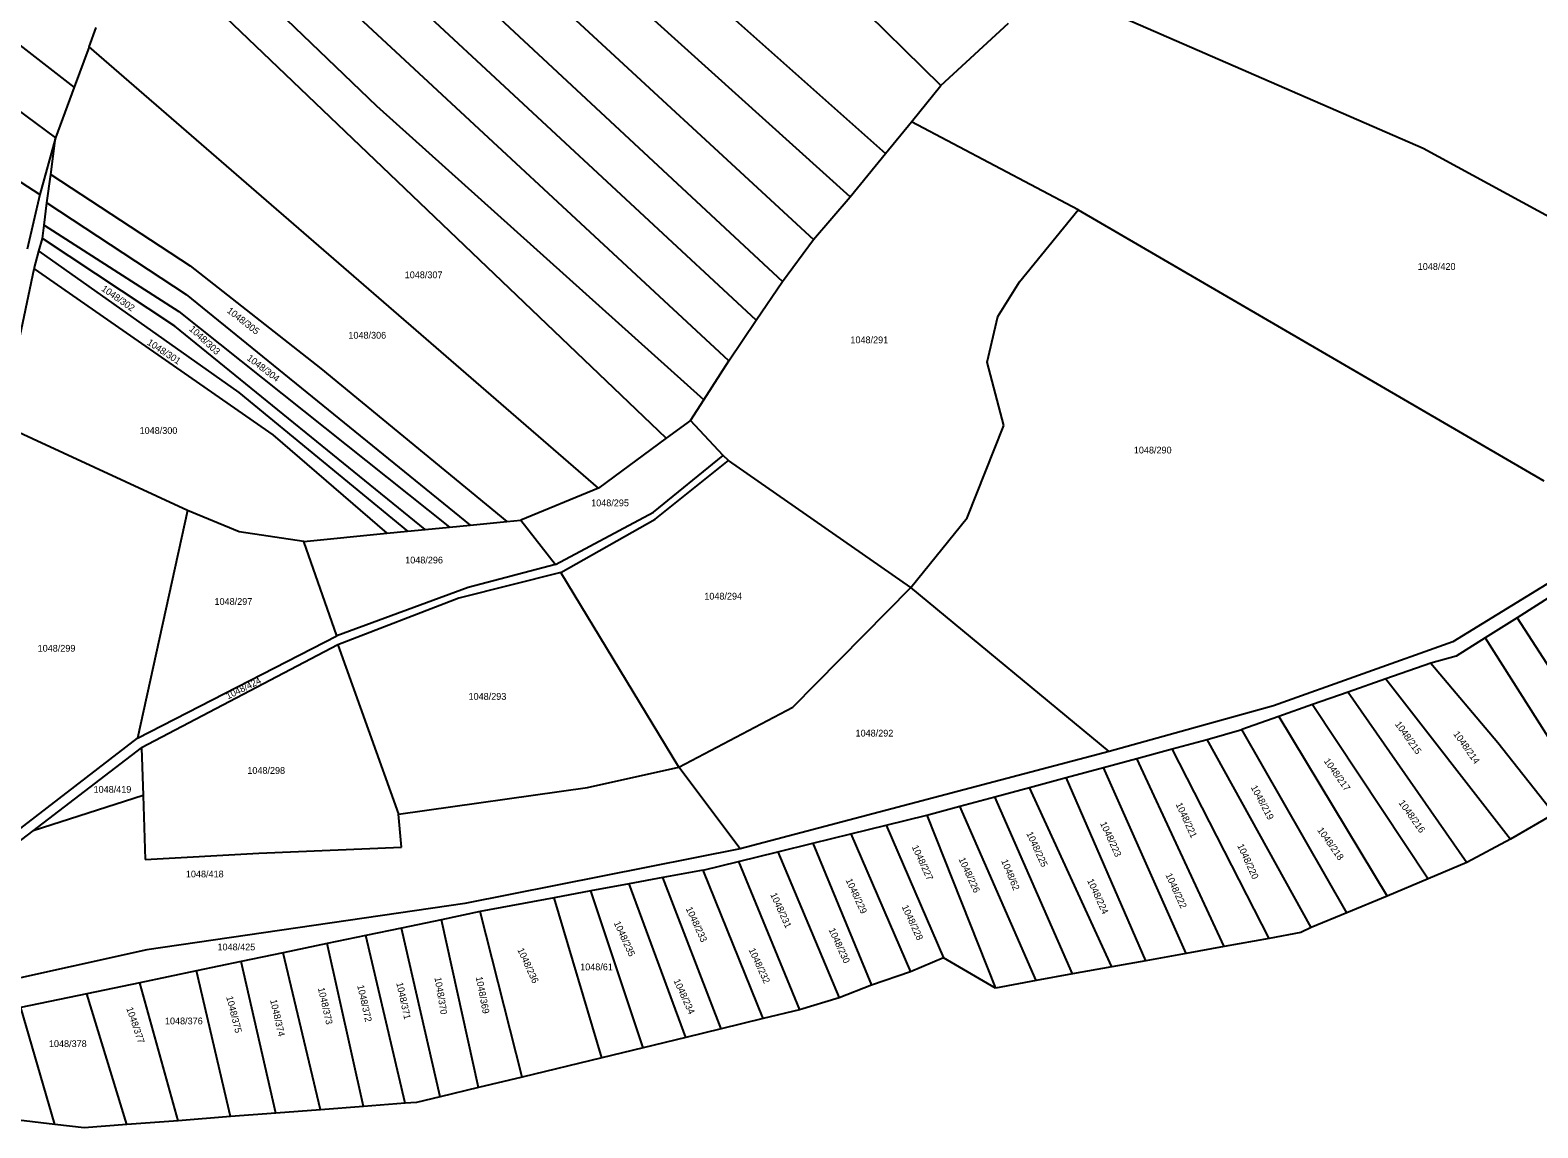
# Model space of a CAD drawing. Extents: x -580630 to -576196, y -1189024 to -1183567.
# Drawn here: x -577659.8 to -577281.4, y -1186719.7 to -1186444.2 of the extents above; entities that cross this region are included whole.
import ezdxf

# ---------------------------------------------------------------- set-up
doc = ezdxf.new("R2010")
doc.units = 0
for name, color, linetype in [('Vrstva 1', 7, 'Continuous'), ('Vrstva 18', 7, 'Continuous'), ('Vrstva 6', 7, 'Continuous')]:
    doc.layers.add(name, color=color, linetype=linetype)

msp = doc.modelspace()

# ---------------------------------------------------------------- linework, layer by layer
at = {"layer": 'Vrstva 1'}
for p, q in [((-577277.78, -1186586.1), (-577286.64, -1186591.67)), ((-577286.64, -1186591.67), (-577294.65, -1186596.71)), ((-577294.65, -1186596.71), (-577301.89, -1186601.27)), ((-577301.89, -1186601.27), (-577308.25, -1186603.03)), ((-577308.25, -1186603.03), (-577291.48, -1186622.95)), ((-577291.48, -1186622.95), (-577277.31, -1186640.88)), ((-577426.5, -1186638.96), (-577417.72, -1186636.58)), ((-577398.18, -1186681.03), (-577417.72, -1186636.58)), ((-577407.33, -1186682.72), (-577426.5, -1186638.96)), ((-577277.31, -1186640.88), (-577288.28, -1186647.21)), ((-577288.28, -1186647.21), (-577299.24, -1186653.09)), ((-577299.24, -1186653.09), (-577308.96, -1186657.2)), ((-577308.96, -1186657.2), (-577319.21, -1186661.48)), ((-577519.08, -1186660.17), (-577528.29, -1186661.93)), ((-577505.98, -1186699.57), (-577519.08, -1186660.17)), ((-577516.38, -1186702.1), (-577528.29, -1186661.93)), ((-577319.21, -1186661.48), (-577329.36, -1186665.67)), ((-577329.36, -1186665.67), (-577338.27, -1186669.41)), ((-577348.86, -1186672.11), (-577360.12, -1186674.15)), ((-577340.93, -1186670.67), (-577348.86, -1186672.11)), ((-577338.27, -1186669.41), (-577340.93, -1186670.67)), ((-577369.67, -1186675.89), (-577379.81, -1186677.73)), ((-577360.12, -1186674.15), (-577369.67, -1186675.89)), ((-577430.58, -1186677), (-577438.85, -1186680.47)), ((-577417.57, -1186684.58), (-577430.58, -1186677)), ((-577388.31, -1186679.27), (-577398.18, -1186681.03)), ((-577379.81, -1186677.73), (-577388.31, -1186679.27)), ((-577448.65, -1186683.86), (-577456.76, -1186687.07)), ((-577438.85, -1186680.47), (-577448.65, -1186683.86)), ((-577407.33, -1186682.72), (-577417.57, -1186684.58)), ((-577398.18, -1186681.03), (-577407.33, -1186682.72)), ((-577456.76, -1186687.07), (-577466.74, -1186690.01)), ((-577466.74, -1186690.01), (-577475.83, -1186692.24)), ((-577486.37, -1186694.8), (-577495.23, -1186696.96)), ((-577475.83, -1186692.24), (-577486.37, -1186694.8)), ((-577495.23, -1186696.96), (-577505.98, -1186699.57)), ((-577516.38, -1186702.1), (-577536.34, -1186706.96)), ((-577505.98, -1186699.57), (-577516.38, -1186702.1)), ((-577547.3, -1186709.57), (-577556.96, -1186711.88)), ((-577536.34, -1186706.96), (-577547.3, -1186709.57)), ((-577576.15, -1186714.3), (-577586.92, -1186715.12)), ((-577565.72, -1186713.5), (-577576.15, -1186714.3)), ((-577562.83, -1186713.28), (-577565.72, -1186713.5)), ((-577556.96, -1186711.88), (-577562.83, -1186713.28)), ((-577653.65, -1186718.79), (-577670.26, -1186716.82)), ((-577622.7, -1186717.86), (-577635.57, -1186718.84)), ((-577609.57, -1186716.85), (-577622.7, -1186717.86)), ((-577598.15, -1186715.98), (-577609.57, -1186716.85)), ((-577586.92, -1186715.12), (-577598.15, -1186715.98)), ((-577646.26, -1186719.66), (-577653.65, -1186718.79)), ((-577635.57, -1186718.84), (-577646.26, -1186719.66))]:
    msp.add_line(p, q, dxfattribs=at)
at = {"layer": 'Vrstva 6'}
for p, q in [((-577589.77, -1186379.94), (-577463.21, -1186496.69)), ((-577454.01, -1186485.99), (-577572.08, -1186379.63)), ((-577602.85, -1186384.5), (-577471.03, -1186507.3)), ((-577477.58, -1186516.94), (-577617.31, -1186387.27)), ((-577572.78, -1186463.24), (-577649.25, -1186389.86)), ((-577484.5, -1186527.2), (-577630.78, -1186391.29)), ((-577522.55, -1186406.3), (-577445.14, -1186475.12)), ((-577431.26, -1186458.1), (-577483.66, -1186406.54)), ((-577500.2, -1186546.6), (-577634.12, -1186418.61)), ((-577648.78, -1186458.48), (-577691.75, -1186425.18)), ((-577705.7, -1186432.42), (-577653.48, -1186471.22)), ((-577403.23, -1186433.27), (-577310.18, -1186473.84)), ((-577645.05, -1186448.38), (-577643.26, -1186443.5)), ((-577431.26, -1186458.1), (-577414.28, -1186442.43)), ((-577645.05, -1186448.38), (-577648.78, -1186458.48)), ((-577517.19, -1186559.12), (-577645.05, -1186448.38)), ((-577648.78, -1186458.48), (-577653.48, -1186471.22)), ((-577438.65, -1186467.16), (-577431.26, -1186458.1)), ((-577490.73, -1186536.97), (-577572.78, -1186463.24)), ((-577445.14, -1186475.12), (-577438.65, -1186467.16)), ((-577396.82, -1186489.29), (-577438.65, -1186467.16)), ((-577681.11, -1186470.11), (-577657.44, -1186485.43)), ((-577653.48, -1186471.22), (-577657.44, -1186485.43)), ((-577654.68, -1186480.42), (-577653.48, -1186471.22)), ((-577454.01, -1186485.99), (-577445.14, -1186475.12)), ((-577310.18, -1186473.84), (-577222.05, -1186521.64)), ((-577655.61, -1186487.52), (-577654.68, -1186480.42)), ((-577654.68, -1186480.42), (-577619.66, -1186503.3)), ((-577657.44, -1186485.43), (-577660.59, -1186499.11)), ((-577463.21, -1186496.69), (-577454.01, -1186485.99)), ((-577656.33, -1186493.09), (-577655.61, -1186487.52)), ((-577655.61, -1186487.52), (-577620.71, -1186510.54)), ((-577411.52, -1186507.32), (-577396.82, -1186489.29)), ((-577396.82, -1186489.29), (-577279.9, -1186557.31)), ((-577656.77, -1186496.44), (-577656.33, -1186493.09)), ((-577656.33, -1186493.09), (-577622.55, -1186514.75)), ((-577657.64, -1186499.65), (-577656.77, -1186496.44)), ((-577623.48, -1186518.44), (-577656.77, -1186496.44)), ((-577471.03, -1186507.3), (-577463.21, -1186496.69)), ((-577658.85, -1186504.08), (-577657.64, -1186499.65)), ((-577657.64, -1186499.65), (-577607.42, -1186535.1)), ((-577667.06, -1186543.16), (-577658.85, -1186504.08)), ((-577658.85, -1186504.08), (-577598.93, -1186545.77)), ((-577619.66, -1186503.3), (-577586.88, -1186529.11)), ((-577477.58, -1186516.94), (-577471.03, -1186507.3)), ((-577416.91, -1186516.08), (-577411.52, -1186507.32)), ((-577620.71, -1186510.54), (-577549.43, -1186568.41)), ((-577622.55, -1186514.75), (-577554.59, -1186568.91)), ((-577484.5, -1186527.2), (-577477.58, -1186516.94)), ((-577419.6, -1186527.54), (-577416.91, -1186516.08)), ((-577560.73, -1186569.51), (-577623.48, -1186518.44)), ((-577490.73, -1186536.97), (-577484.5, -1186527.2)), ((-577415.42, -1186543.38), (-577419.6, -1186527.54)), ((-577586.88, -1186529.11), (-577540.16, -1186567.5)), ((-577607.42, -1186535.1), (-577565.14, -1186569.95)), ((-577494.11, -1186542.12), (-577490.73, -1186536.97)), ((-577620.3, -1186564.71), (-577667.06, -1186543.16)), ((-577494.11, -1186542.12), (-577500.2, -1186546.6)), ((-577485.86, -1186550.96), (-577494.11, -1186542.12)), ((-577424.63, -1186566.57), (-577415.42, -1186543.38)), ((-577598.93, -1186545.77), (-577570.3, -1186570.45)), ((-577500.2, -1186546.6), (-577517.19, -1186559.12)), ((-577503.37, -1186565.18), (-577485.86, -1186550.96)), ((-577484.57, -1186552.19), (-577485.86, -1186550.96)), ((-577502.98, -1186566.94), (-577484.57, -1186552.19)), ((-577438.76, -1186584.06), (-577484.57, -1186552.19)), ((-577517.19, -1186559.12), (-577536.66, -1186567.16)), ((-577620.3, -1186564.71), (-577632.87, -1186621.83)), ((-577607.34, -1186570.07), (-577620.3, -1186564.71)), ((-577527.98, -1186578.29), (-577503.37, -1186565.18)), ((-577438.76, -1186584.06), (-577424.63, -1186566.57)), ((-577591.16, -1186572.49), (-577607.34, -1186570.07)), ((-577591.16, -1186572.49), (-577570.3, -1186570.45)), ((-577570.3, -1186570.45), (-577565.14, -1186569.95)), ((-577565.14, -1186569.95), (-577560.73, -1186569.51)), ((-577560.73, -1186569.51), (-577554.59, -1186568.91)), ((-577554.59, -1186568.91), (-577549.43, -1186568.41)), ((-577549.43, -1186568.41), (-577540.16, -1186567.5)), ((-577540.16, -1186567.5), (-577536.66, -1186567.16)), ((-577536.66, -1186567.16), (-577527.98, -1186578.29)), ((-577526.63, -1186580.31), (-577502.98, -1186566.94)), ((-577582.87, -1186596.15), (-577591.16, -1186572.49)), ((-577526.63, -1186580.31), (-577552.23, -1186586.72)), ((-577527.98, -1186578.29), (-577549.87, -1186584.02)), ((-577497, -1186629.18), (-577526.63, -1186580.31)), ((-577549.87, -1186584.02), (-577582.87, -1186596.15)), ((-577468.4, -1186614.05), (-577438.76, -1186584.06)), ((-577388.98, -1186625.22), (-577438.76, -1186584.06)), ((-577276.97, -1186581.88), (-577302.76, -1186597.69)), ((-577552.23, -1186586.72), (-577582.6, -1186598.42)), ((-577286.64, -1186591.67), (-577269.26, -1186618.5)), ((-577632.87, -1186621.83), (-577582.87, -1186596.15)), ((-577294.65, -1186596.71), (-577277.24, -1186624.1)), ((-577582.6, -1186598.42), (-577631.87, -1186624.32)), ((-577582.6, -1186598.42), (-577567.34, -1186640.96)), ((-577302.76, -1186597.69), (-577347.78, -1186613.75)), ((-577308.25, -1186603.03), (-577319.58, -1186607)), ((-577319.58, -1186607), (-577329.02, -1186610.3)), ((-577319.58, -1186607), (-577288.28, -1186647.21)), ((-577329.02, -1186610.3), (-577337.96, -1186613.43)), ((-577329.02, -1186610.3), (-577299.24, -1186653.09)), ((-577497, -1186629.18), (-577468.4, -1186614.05)), ((-577347.78, -1186613.75), (-577388.98, -1186625.22)), ((-577337.96, -1186613.43), (-577346.43, -1186616.4)), ((-577337.96, -1186613.43), (-577308.96, -1186657.2)), ((-577364.38, -1186622.16), (-577355.74, -1186619.66)), ((-577346.43, -1186616.4), (-577355.74, -1186619.66)), ((-577329.36, -1186665.67), (-577355.74, -1186619.66)), ((-577346.43, -1186616.4), (-577319.21, -1186661.48)), ((-577684.08, -1186661.26), (-577632.87, -1186621.83)), ((-577373.16, -1186624.53), (-577364.38, -1186622.16)), ((-577338.27, -1186669.41), (-577364.38, -1186622.16)), ((-577659.08, -1186645.09), (-577631.87, -1186624.32)), ((-577631.87, -1186624.32), (-577631.48, -1186636.25)), ((-577388.98, -1186625.22), (-577481.66, -1186649.65)), ((-577390.45, -1186629.21), (-577382.04, -1186626.94)), ((-577382.04, -1186626.94), (-577373.16, -1186624.53)), ((-577360.12, -1186674.15), (-577382.04, -1186626.94)), ((-577348.86, -1186672.11), (-577373.16, -1186624.53)), ((-577519.96, -1186634.24), (-577497, -1186629.18)), ((-577481.66, -1186649.65), (-577497, -1186629.18)), ((-577399.77, -1186631.73), (-577390.45, -1186629.21)), ((-577369.67, -1186675.89), (-577390.45, -1186629.21)), ((-577567.34, -1186640.96), (-577519.96, -1186634.24)), ((-577417.72, -1186636.58), (-577409.02, -1186634.23)), ((-577409.02, -1186634.23), (-577399.77, -1186631.73)), ((-577388.31, -1186679.27), (-577409.02, -1186634.23)), ((-577379.81, -1186677.73), (-577399.77, -1186631.73)), ((-577631.48, -1186636.25), (-577659.08, -1186645.09)), ((-577631.48, -1186636.25), (-577630.96, -1186652.29)), ((-577566.6, -1186649.26), (-577567.34, -1186640.96)), ((-577444.96, -1186643.69), (-577434.76, -1186641.19)), ((-577434.76, -1186641.19), (-577426.5, -1186638.96)), ((-577434.76, -1186641.19), (-577417.57, -1186684.58)), ((-577686.2, -1186665.78), (-577659.08, -1186645.09)), ((-577463.41, -1186648.22), (-577453.81, -1186645.87)), ((-577453.81, -1186645.87), (-577444.96, -1186643.69)), ((-577453.81, -1186645.87), (-577438.85, -1186680.47)), ((-577444.96, -1186643.69), (-577430.58, -1186677)), ((-577602.4, -1186650.75), (-577566.6, -1186649.26)), ((-577481.66, -1186649.65), (-577550.71, -1186663.38)), ((-577472.2, -1186650.38), (-577463.41, -1186648.22)), ((-577463.41, -1186648.22), (-577448.65, -1186683.86)), ((-577630.96, -1186652.29), (-577602.4, -1186650.75)), ((-577490.89, -1186654.97), (-577482.01, -1186652.79)), ((-577482.01, -1186652.79), (-577472.2, -1186650.38)), ((-577482.01, -1186652.79), (-577466.74, -1186690.01)), ((-577472.2, -1186650.38), (-577456.76, -1186687.07)), ((-577501.03, -1186656.86), (-577509.51, -1186658.44)), ((-577490.89, -1186654.97), (-577501.03, -1186656.86)), ((-577486.37, -1186694.8), (-577501.03, -1186656.86)), ((-577475.83, -1186692.24), (-577490.89, -1186654.97)), ((-577509.51, -1186658.44), (-577519.08, -1186660.17)), ((-577495.23, -1186696.96), (-577509.51, -1186658.44)), ((-577550.71, -1186663.38), (-577630.52, -1186675)), ((-577528.29, -1186661.93), (-577546.92, -1186665.4)), ((-577556.63, -1186667.43), (-577566.66, -1186669.53)), ((-577546.92, -1186665.4), (-577556.63, -1186667.43)), ((-577547.3, -1186709.57), (-577556.63, -1186667.43)), ((-577536.34, -1186706.96), (-577546.92, -1186665.4)), ((-577575.57, -1186671.39), (-577585.3, -1186673.42)), ((-577566.66, -1186669.53), (-577575.57, -1186671.39)), ((-577565.72, -1186713.5), (-577575.57, -1186671.39)), ((-577556.96, -1186711.88), (-577566.66, -1186669.53)), ((-577630.52, -1186675), (-577681.26, -1186686.16)), ((-577596.32, -1186675.72), (-577606.9, -1186677.93)), ((-577585.3, -1186673.42), (-577596.32, -1186675.72)), ((-577586.92, -1186715.12), (-577596.32, -1186675.72)), ((-577576.15, -1186714.3), (-577585.3, -1186673.42)), ((-577606.9, -1186677.93), (-577618.05, -1186680.26)), ((-577598.15, -1186715.98), (-577606.9, -1186677.93)), ((-577632.34, -1186683.25), (-577645.62, -1186686.02)), ((-577618.05, -1186680.26), (-577632.34, -1186683.25)), ((-577622.7, -1186717.86), (-577632.34, -1186683.25)), ((-577609.57, -1186716.85), (-577618.05, -1186680.26)), ((-577645.62, -1186686.02), (-577662.17, -1186689.48)), ((-577635.57, -1186718.84), (-577645.62, -1186686.02)), ((-577653.65, -1186718.79), (-577662.17, -1186689.48))]:
    msp.add_line(p, q, dxfattribs=at)

# ---------------------------------------------------------------- texts
at = {"layer": 'Vrstva 18'}
for s, p in [('1048/307', (-577565.82, -1186506.44)), ('1048/420', (-577311.557, -1186504.35)), ('1048/306', (-577579.96, -1186521.6)), ('1048/291', (-577453.952, -1186522.76)), ('1048/300', (-577632.367, -1186545.51)), ('1048/290', (-577382.817, -1186550.42)), ('1048/295', (-577519.027, -1186563.67)), ('1048/296', (-577565.7, -1186578.02)), ('1048/294', (-577490.63, -1186587.09)), ('1048/297', (-577613.56, -1186588.42)), ('1048/299', (-577657.96, -1186600.16)), ('1048/293', (-577549.797, -1186612.24)), ('1048/292', (-577452.664, -1186621.46)), ('1048/298', (-577605.33, -1186630.82)), ('1048/419', (-577643.918, -1186635.57)), ('1048/418', (-577620.749, -1186656.81)), ('1048/425', (-577612.817, -1186675.12)), ('1048/61', (-577521.779, -1186680.12)), ('1048/376', (-577626.003, -1186693.68)), ('1048/378', (-577655.123, -1186699.39))]:
    msp.add_text(s, height=1.7, dxfattribs=at).set_placement(p)
for s, rotation, p in [('1048/302', 324.98166, (-577642.107, -1186509.425)), ('1048/305', 321.94499, (-577610.586, -1186514.872)), ('1048/303', 317.18944, (-577620.067, -1186519.375)), ('1048/301', 326.58594, (-577630.65, -1186522.952)), ('1048/304', 322.63253, (-577605.588, -1186526.801)), ('1048/424', 26.35606, (-577610.181, -1186612.174)), ('1048/215', 305.55839, (-577317.365, -1186618.379)), ('1048/214', 305.55839, (-577302.728, -1186620.818)), ('1048/217', 305.55839, (-577335.225, -1186627.63)), ('1048/219', 298.10994, (-577353.514, -1186634.21)), ('1048/221', 294.67219, (-577372.35, -1186638.471)), ('1048/216', 305.55839, (-577316.448, -1186638.118)), ('1048/225', 294.67219, (-577409.844, -1186645.782)), ('1048/223', 294.67219, (-577391.331, -1186643.246)), ('1048/218', 305.55839, (-577336.87, -1186644.971)), ('1048/227', 294.67219, (-577438.588, -1186649.161)), ('1048/220', 294.67219, (-577356.906, -1186648.831)), ('1048/226', 294.67219, (-577426.845, -1186652.245)), ('1048/62', 292.66684, (-577416.149, -1186652.664)), ('1048/229', 294.67219, (-577455.185, -1186657.505)), ('1048/224', 294.67219, (-577394.585, -1186657.595)), ('1048/222', 294.67219, (-577374.926, -1186656.188)), ('1048/231', 294.67219, (-577474.115, -1186661.109)), ('1048/233', 294.67219, (-577495.317, -1186664.634)), ('1048/228', 294.67219, (-577441.113, -1186664.177)), ('1048/235', 294.67219, (-577513.39, -1186668.24)), ('1048/230', 294.67219, (-577459.472, -1186669.948)), ('1048/236', 294.67219, (-577537.6, -1186674.963)), ('1048/232', 294.67219, (-577479.541, -1186674.986)), ('1048/372', 282.64008, (-577577.766, -1186683.972)), ('1048/371', 282.4109, (-577567.954, -1186683.319)), ('1048/370', 279.6607, (-577558.356, -1186681.975)), ('1048/369', 281.0358, (-577547.993, -1186681.844)), ('1048/234', 294.67219, (-577498.4, -1186682.723)), ('1048/375', 284.41625, (-577610.65, -1186686.817)), ('1048/374', 282.98386, (-577599.62, -1186687.631)), ('1048/373', 282.92656, (-577587.625, -1186684.625)), ('1048/377', 288.88532, (-577635.727, -1186689.677))]:
    msp.add_text(s, height=1.7, rotation=rotation, dxfattribs=at).set_placement(p)

doc.saveas('drawing.dxf')
